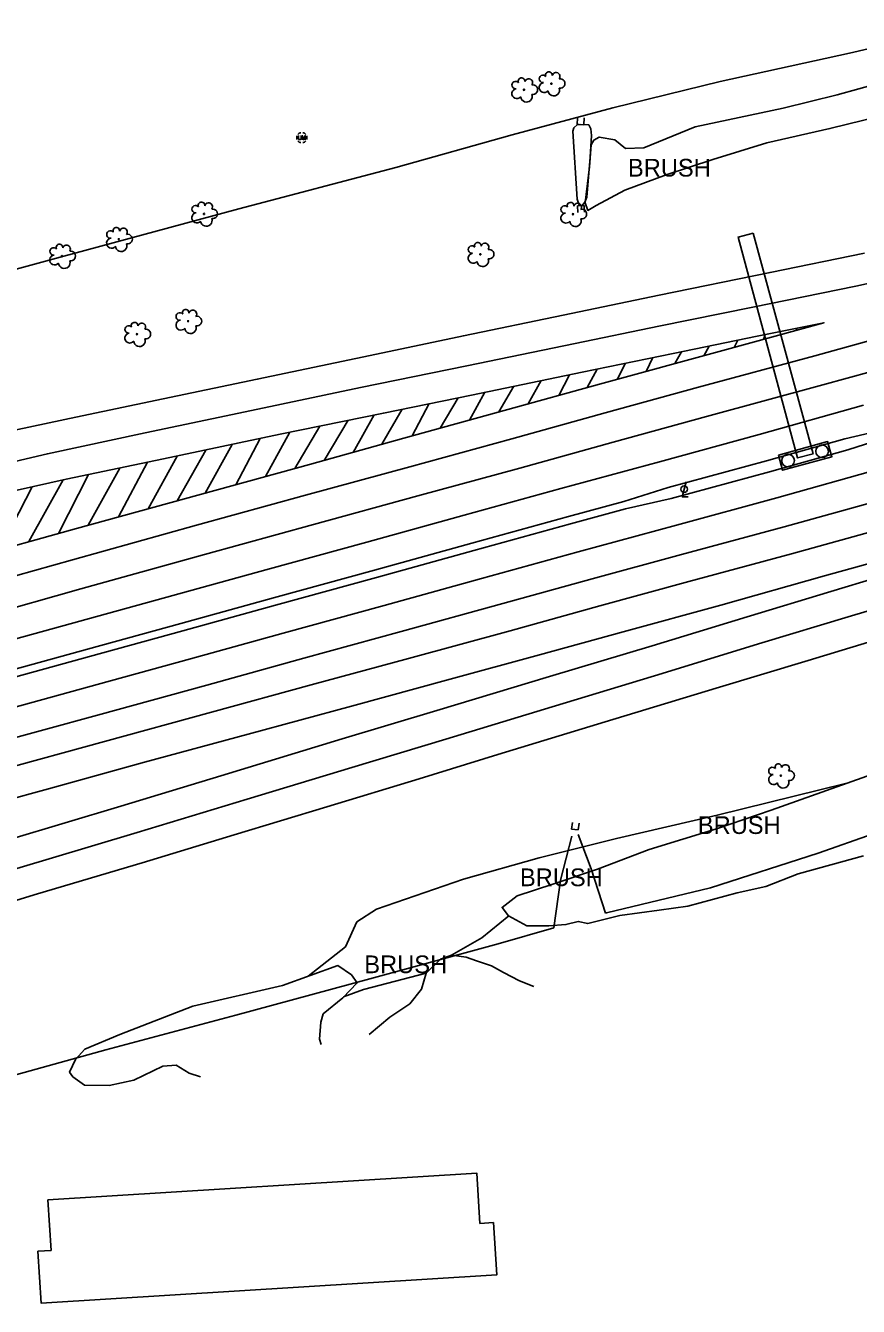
# Model space of a CAD drawing. Extents: x 2129547 to 2134906, y 657330 to 659734.
# Drawn here: x 2133745 to 2134075, y 658623 to 659130 of the extents above; entities that cross this region are included whole.
import ezdxf

# ---------------------------------------------------------------- set-up
doc = ezdxf.new("R2010")
doc.units = 0
for name, color, linetype in [('BD_X_Building', 7, 'Continuous'), ('Default', 7, 'Continuous'), ('DR_X_Culvert', 7, 'Continuous'), ('HY_X_Water_Edge', 7, 'Continuous'), ('LT_X_Poles', 7, 'Continuous'), ('PM_X_Edge_Line', 7, 'Continuous'), ('PM_X_Lane_Line', 7, 'Continuous'), ('PM_X_Transverse_Line', 7, 'Continuous'), ('PV_X_EOP2', 7, 'Continuous'), ('RD_X_Concrete_Barrier', 7, 'Continuous'), ('RD_X_Fence', 7, 'Continuous'), ('SN_X_Foundation', 7, 'Continuous'), ('SN_X_Truss_Overhead', 7, 'Continuous'), ('UT_X_Unknown_Cells', 7, 'Continuous'), ('VG_X_Cells', 7, 'Continuous'), ('VG_X_Shrub_Line_Lt', 7, 'Continuous'), ('VG_X_Text', 7, 'Continuous'), ('VG_X_Tree_Line_Lt', 7, 'Continuous')]:
    doc.layers.add(name, color=color, linetype=linetype)

# ---------------------------------------------------------------- blocks, each defined once
blk = doc.blocks.new('PIPE')
at = {"layer": 'Default'}
for p, q in [((0.135, 0.067), (0, 0.067)), ((0, 0.067), (0, -0.067)), ((0, -0.067), (0.135, -0.067))]:
    blk.add_line(p, q, dxfattribs=at)
blk = doc.blocks.new('LPOLE')
at = {"layer": 'LT_X_Poles'}
blk.add_lwpolyline([(0.01, 0.0375), (-0.01, -0.0385), (0.02, -0.0385)], dxfattribs=at)
blk.add_circle((0, 0), 0.0165, dxfattribs=at)
blk = doc.blocks.new('TREE')
at = {"layer": 'VG_X_Cells'}
blk.add_circle((0, 0), 0.00305, dxfattribs=at)
for centre, radius, start, end in [((-0.0362, -0.0197), 0.0251, 96.17219, 320.57371), ((-0.042, 0.0237), 0.0187, 39.06254, 279.54124), ((-0.0125, 0.0428), 0.0167, 354.0047, 205.97412), ((0.0232, 0.0359), 0.0197, 323.82996, 165.0376), ((0.0439, 0.0005), 0.0243, 259.14531, 101.45961), ((0.012, -0.0331), 0.029, 184.94757, 19.45715)]:
    blk.add_arc(centre, radius, start, end, dxfattribs=at)
blk = doc.blocks.new('UMH')
at = {"layer": 'UT_X_Unknown_Cells'}
for p, q in [((-0.017, 0.0104), (-0.017, -0.0059)), ((-0.0042, 0.0104), (-0.0042, -0.0059))]:
    blk.add_line(p, q, dxfattribs=at)
blk.add_lwpolyline([(0.0024, -0.01), (0.0024, 0.0104), (0.0099, -0.01), (0.0174, 0.0104), (0.0174, -0.01)], dxfattribs=at)
for centre, radius, start, end in [((0, 0), 0.0254, 160.01689, 200.03919), ((0, 0), 0.0254, 100.0806, 140.07213), ((0, 0), 0.0254, 40.05767, 80.10608), ((0, 0), 0.0254, 340.01689, 20.03919), ((0, 0), 0.0254, 220.05767, 260.04731), ((-0.0106, -0.0029), 0.00708, 205.19243, 334.80757), ((0, 0), 0.0254, 280.01144, 320.02638)]:
    blk.add_arc(centre, radius, start, end, dxfattribs=at)
blk = doc.blocks.new('POINT_DISPLAY')
at = {"layer": 'Default'}
blk.add_line((0, 0), (0, 0), dxfattribs=at)
blk = doc.blocks.new('STFN_7.65-57X')
at = {"layer": 'Default'}
blk.add_lwpolyline([(-1.027, 0.318), (1.027, 0.318), (1.027, -0.317), (-1.027, -0.317)], close=True, dxfattribs=at)
for centre in [(-0.709, 0), (0.709, 0)]:
    blk.add_circle(centre, 0.254, dxfattribs=at)
blk.add_blockref('POINT_DISPLAY', (0, 0), dxfattribs=at)

msp = doc.modelspace()

# ---------------------------------------------------------------- linework, layer by layer
at = {"layer": 'BD_X_Building'}
msp.add_lwpolyline([(2133753.79, 658665.45), (2133923.53, 658676), (2133924.77, 658656.08), (2133930.12, 658656.42), (2133931.41, 658635.72), (2133751.11, 658624.52), (2133749.83, 658645.09), (2133755.03, 658645.41)], close=True, dxfattribs=at)
at = {"layer": 'HY_X_Water_Edge'}
for points in [[(2133964.19, 659058.89), (2133963.21, 659061.53), (2133961.53, 659088.43), (2133961.95, 659089.65), (2133963.33, 659091.05), (2133964.03, 659091.04)], [(2133965.25, 659058.94), (2133966.24, 659060.31), (2133967.09, 659062.25), (2133968.4, 659078.09), (2133968.88, 659086.71), (2133968.68, 659089.37), (2133967.8, 659090.87), (2133964.39, 659091)]]:
    msp.add_lwpolyline(points, dxfattribs=at)
at = {"layer": 'PM_X_Edge_Line'}
for points in [[(2134076.98, 659040.11), (2134039.58, 659032.47), (2133995.73, 659023.51), (2133957.76, 659015.59), (2133918.23, 659007.39), (2133881.38, 658999.63), (2133836.62, 658990.22), (2133799.43, 658982.49), (2133764.9, 658975.21), (2133735.74, 658968.93), (2133703.2, 658961.23), (2133666.48, 658951.71), (2133630.91, 658941.98), (2133596.74, 658932.79), (2133563.73, 658923.72), (2133529.99, 658914.34), (2133494.1, 658904.34), (2133466.6, 658896.85), (2133432.86, 658887.72), (2133403.89, 658879.94), (2133374.41, 658872.42), (2133346.49, 658865.44), (2133329.04, 658861.1), (2133300.92, 658854.17)], [(2133722.33, 658919.3), (2133765.05, 658931.14), (2133807.8, 658942.86), (2133857.32, 658956.46), (2133894.64, 658966.9), (2133935.83, 658978.22), (2133972.12, 658988.26), (2134020.83, 659001.53), (2134060.85, 659012.54), (2134034.42, 659007.23), (2134001.29, 659000.44), (2133965.24, 658993), (2133921.46, 658983.96), (2133886.55, 658976.83), (2133845.67, 658968.4), (2133799.54, 658958.66), (2133761.03, 658950.6), (2133728.54, 658943.33)], [(2133309.7, 658768.6), (2133347.5, 658778.96), (2133367.51, 658784.47), (2133405.62, 658795.16), (2133448.61, 658806.96), (2133483.46, 658816.51), (2133522.93, 658827.51), (2133562.53, 658838.54), (2133602.55, 658849.42), (2133643.3, 658860.47), (2133686.86, 658872.53), (2133725.64, 658883.22), (2133766.44, 658894.43), (2133803.3, 658904.62), (2133840.04, 658914.78), (2133879.97, 658925.74), (2133918.52, 658936.37), (2133956.82, 658946.94), (2133995.76, 658957.55), (2134035.26, 658968.3), (2134076.56, 658979.89)], [(2134083.48, 658954.83), (2134042.19, 658943.24), (2134002.59, 658932.46), (2133963.69, 658921.87), (2133925.43, 658911.31), (2133886.87, 658900.67), (2133846.95, 658889.72), (2133810.23, 658879.56), (2133773.34, 658869.36), (2133732.54, 658858.16), (2133693.78, 658847.47), (2133650.17, 658835.4), (2133609.36, 658824.33), (2133569.43, 658813.47), (2133529.91, 658802.46), (2133490.38, 658791.45), (2133455.49, 658781.89), (2133412.58, 658770.11), (2133374.05, 658759.3), (2133354.39, 658753.89), (2133316.59, 658743.53), (2133275.25, 658732.12)], [(2133283.96, 658698.16), (2133325.94, 658709.93), (2133362.52, 658720.04), (2133382.76, 658725.75), (2133415.39, 658734.86), (2133446.49, 658743.43), (2133481, 658753.01), (2133515.88, 658762.68), (2133547.13, 658771.3), (2133583.28, 658781.31), (2133617.02, 658790.56), (2133648.77, 658799.18), (2133685.56, 658809.34), (2133717.23, 658818.06), (2133753.97, 658828.1), (2133791.98, 658838.6), (2133832.99, 658849.73), (2133873.96, 658860.85), (2133913, 658871.48), (2133948.28, 658881.16), (2133981.44, 658890.27), (2134020.14, 658900.81), (2134061.11, 658912.35), (2134098.82, 658922.76)], [(2134100.25, 658917.23), (2134063.61, 658906.19), (2134030.5, 658896.13), (2133992.93, 658884.72), (2133952.23, 658872.51), (2133907.65, 658859.14), (2133870.19, 658847.84), (2133822.17, 658833.24), (2133782.71, 658821.22), (2133738.55, 658807.98), (2133692.7, 658794.41), (2133654.59, 658783.4), (2133617.25, 658772.7), (2133577.18, 658761.03), (2133541.61, 658750.79), (2133494, 658737.03), (2133462.99, 658727.98), (2133431.79, 658718.75), (2133387.92, 658705.89), (2133365.27, 658699.28), (2133330.15, 658689.11), (2133297.63, 658679.74)], [(2133300.81, 658650.13), (2133340.17, 658662.31), (2133370.93, 658671.87), (2133394.87, 658679.11), (2133427.09, 658689.08), (2133460.97, 658699.4), (2133496.37, 658710.22), (2133532.31, 658721.07), (2133564.53, 658730.83), (2133600.72, 658741.62), (2133635.89, 658752.26), (2133677.52, 658764.71), (2133710.02, 658774.41), (2133749.64, 658786.47), (2133791.16, 658798.85), (2133827.56, 658809.83), (2133864.21, 658820.91), (2133900.69, 658832.03), (2133931.82, 658841.63), (2133974.36, 658854.66), (2134018.27, 658867.93), (2134054.66, 658878.9), (2134088.9, 658889.31)]]:
    msp.add_lwpolyline(points, dxfattribs=at)
at = {"layer": 'PM_X_Lane_Line'}
for points in [[(2134118.93, 659037.07), (2134073.54, 659027.1), (2134032.75, 659018.71), (2133995.61, 659011.27), (2133962.39, 659004.33), (2133919.52, 658995.52), (2133877.54, 658986.95), (2133831.82, 658977.28), (2133792.35, 658968.95), (2133753.58, 658960.7), (2133718.63, 658952.54), (2133687.93, 658944.98), (2133659.01, 658937.36), (2133625.24, 658928.09), (2133585.58, 658917.3), (2133543.69, 658905.93), (2133507.33, 658895.86), (2133466.3, 658884.59), (2133424.01, 658873.52), (2133383.54, 658862.9), (2133349.44, 658854.08), (2133325.82, 658848.04), (2133297.69, 658840.83)], [(2133313.7, 658795.31), (2133339, 658802.3), (2133361.28, 658808.47), (2133395.15, 658817.54), (2133438.07, 658829.18), (2133482.76, 658841.53), (2133526.2, 658853.67), (2133575.25, 658867.16), (2133621.71, 658879.84), (2133678.02, 658895.07), (2133725.8, 658908.19), (2133763.55, 658918.78), (2133812.61, 658932.39), (2133855.72, 658944.34), (2133897.07, 658955.57), (2133937.39, 658966.63), (2133974.36, 658976.85), (2134011.24, 658987.04), (2134057.34, 658999.52), (2134095.74, 659010.12)], [(2134098.91, 658998.55), (2134060.5, 658987.95), (2134014.41, 658975.46), (2133977.55, 658965.28), (2133940.57, 658955.06), (2133900.23, 658943.99), (2133858.89, 658932.76), (2133815.81, 658920.83), (2133766.78, 658907.22), (2133728.61, 658896.45), (2133681.16, 658883.49), (2133624.85, 658868.26), (2133578.42, 658855.58), (2133529.4, 658842.11), (2133485.97, 658829.97), (2133441.24, 658817.61), (2133398.31, 658805.97), (2133364.46, 658796.21), (2133347.75, 658791.48), (2133325.2, 658785.49), (2133298.77, 658778.04)], [(2134082.7, 658942.15), (2134045.11, 658931.76), (2134004.55, 658920.87), (2133969.21, 658911.2), (2133933.79, 658901.38), (2133893.59, 658890.3), (2133855.02, 658879.79), (2133816.65, 658869.07), (2133773.41, 658857.23), (2133730.82, 658845.66), (2133696.89, 658836.35), (2133666.57, 658827.89), (2133635.33, 658819.28), (2133597.94, 658809.08), (2133562.69, 658799.56), (2133526.89, 658789.25), (2133487.16, 658778.31), (2133449.31, 658767.99), (2133406.68, 658756.3), (2133376.98, 658748.02), (2133351.87, 658741.08), (2133319.94, 658732.31), (2133288.5, 658723.61)], [(2134085.69, 658931.46), (2134048.03, 658921.05), (2134007.46, 658910.16), (2133972.15, 658900.5), (2133936.74, 658890.68), (2133896.5, 658879.69), (2133857.94, 658869.19), (2133818.5, 658858.38), (2133776.26, 658846.81), (2133733.66, 658835.25), (2133699.77, 658825.94), (2133669.46, 658817.48), (2133638.19, 658808.87), (2133600.77, 658798.65), (2133565.6, 658789.16), (2133529.81, 658778.86), (2133490.02, 658767.9), (2133452.16, 658757.57), (2133409.55, 658745.89), (2133379.74, 658737.38), (2133360.24, 658732.07), (2133330.22, 658723.85), (2133298.5, 658714.96)], [(2133285.43, 658660.84), (2133325.6, 658673.06), (2133366.78, 658685.54), (2133391.32, 658692.78), (2133423.26, 658702.17), (2133460.05, 658712.86), (2133499.85, 658724.58), (2133554.8, 658740.88), (2133599.29, 658754.21), (2133636.1, 658765.28), (2133676.03, 658777.16), (2133716.18, 658788.97), (2133754.3, 658800.38), (2133789.1, 658810.81), (2133832.71, 658824.03), (2133874.01, 658836.57), (2133911.3, 658847.78), (2133953.4, 658860.48), (2133993.83, 658872.75), (2134036.36, 658885.82), (2134070.45, 658896.19), (2134110.34, 658908.07)]]:
    msp.add_lwpolyline(points, dxfattribs=at)
at = {"layer": 'PM_X_Transverse_Line'}
for p, q in [((2134036.98, 659005.98), (2134037.61, 659007.87)), ((2134049.85, 659009.52), (2134050.12, 659010.39)), ((2134013.42, 658999.52), (2134015.51, 659003.35)), ((2134025.38, 659002.78), (2134026.84, 659005.68)), ((2133990.54, 658993.28), (2133993.18, 658998.77)), ((2134001.92, 658996.38), (2134004.51, 659001.1)), ((2133955.94, 658983.79), (2133960.22, 658991.96)), ((2133967.2, 658986.9), (2133971.21, 658994.23)), ((2133979.04, 658990.15), (2133982.42, 658996.55)), ((2133932.27, 658977.24), (2133938.13, 658987.4)), ((2133943.88, 658980.45), (2133949, 658989.65)), ((2133909.08, 658970.87), (2133916.15, 658982.87)), ((2133920.66, 658974.05), (2133926.68, 658985.04)), ((2133885.99, 658964.49), (2133893.98, 658978.35)), ((2133897.94, 658967.81), (2133904.73, 658980.54)), ((2133851.55, 658954.88), (2133861.45, 658971.65)), ((2133863.12, 658958.09), (2133872.61, 658973.96)), ((2133874.66, 658961.2), (2133882.87, 658976.07)), ((2133828.15, 658948.45), (2133837.79, 658966.74)), ((2133839.97, 658951.7), (2133849.56, 658969.2)), ((2133805.01, 658942.09), (2133816.26, 658962.19)), ((2133816, 658945.11), (2133826.72, 658964.4)), ((2133781.78, 658935.73), (2133793.2, 658957.33)), ((2133793.45, 658938.93), (2133804.95, 658959.8)), ((2133758.04, 658929.2), (2133769.86, 658952.45)), ((2133769.76, 658932.43), (2133782.3, 658955.05)), ((2133734.58, 658922.69), (2133747.58, 658947.59)), ((2133746.3, 658925.94), (2133759.81, 658950.33))]:
    msp.add_line(p, q, dxfattribs=at)
at = {"layer": 'PV_X_EOP2'}
for points in [[(2134076.98, 659040.11), (2134039.58, 659032.47), (2133995.73, 659023.51), (2133957.76, 659015.59), (2133918.23, 659007.39), (2133881.38, 658999.63), (2133836.62, 658990.22), (2133799.43, 658982.49), (2133764.9, 658975.21), (2133735.74, 658968.93), (2133703.2, 658961.23), (2133666.48, 658951.71), (2133630.91, 658941.98), (2133596.74, 658932.79), (2133563.73, 658923.72), (2133529.99, 658914.34), (2133494.1, 658904.34), (2133466.6, 658896.85), (2133432.86, 658887.72), (2133403.89, 658879.94), (2133374.41, 658872.42), (2133346.49, 658865.44), (2133329.04, 658861.1), (2133300.92, 658854.17)], [(2133722.33, 658919.3), (2133765.05, 658931.14), (2133807.8, 658942.86), (2133857.32, 658956.46), (2133894.64, 658966.9), (2133935.83, 658978.22), (2133972.12, 658988.26), (2134020.83, 659001.53), (2134060.85, 659012.54), (2134034.42, 659007.23), (2134001.29, 659000.44), (2133965.24, 658993), (2133921.46, 658983.96), (2133886.55, 658976.83), (2133845.67, 658968.4), (2133799.54, 658958.66), (2133761.03, 658950.6), (2133728.54, 658943.33)], [(2133309.7, 658768.6), (2133347.5, 658778.96), (2133367.51, 658784.47), (2133405.62, 658795.16), (2133448.61, 658806.96), (2133483.46, 658816.51), (2133522.93, 658827.51), (2133562.53, 658838.54), (2133602.55, 658849.42), (2133643.3, 658860.47), (2133686.86, 658872.53), (2133725.64, 658883.22), (2133766.44, 658894.43), (2133803.3, 658904.62), (2133840.04, 658914.78), (2133879.97, 658925.74), (2133918.52, 658936.37), (2133956.82, 658946.94), (2133995.76, 658957.55), (2134035.26, 658968.3), (2134076.56, 658979.89)], [(2134083.48, 658954.83), (2134042.19, 658943.24), (2134002.59, 658932.46), (2133963.69, 658921.87), (2133925.43, 658911.31), (2133886.87, 658900.67), (2133846.95, 658889.72), (2133810.23, 658879.56), (2133773.34, 658869.36), (2133732.54, 658858.16), (2133693.78, 658847.47), (2133650.17, 658835.4), (2133609.36, 658824.33), (2133569.43, 658813.47), (2133529.91, 658802.46), (2133490.38, 658791.45), (2133455.49, 658781.89), (2133412.58, 658770.11), (2133374.05, 658759.3), (2133354.39, 658753.89), (2133316.59, 658743.53), (2133275.25, 658732.12)], [(2133283.96, 658698.16), (2133325.94, 658709.93), (2133362.52, 658720.04), (2133382.76, 658725.75), (2133415.39, 658734.86), (2133446.49, 658743.43), (2133481, 658753.01), (2133515.88, 658762.68), (2133547.13, 658771.3), (2133583.28, 658781.31), (2133617.02, 658790.56), (2133648.77, 658799.18), (2133685.56, 658809.34), (2133717.23, 658818.06), (2133753.97, 658828.1), (2133791.98, 658838.6), (2133832.99, 658849.73), (2133873.96, 658860.85), (2133913, 658871.48), (2133948.28, 658881.16), (2133981.44, 658890.27), (2134020.14, 658900.81), (2134061.11, 658912.35), (2134098.82, 658922.76)], [(2134100.25, 658917.23), (2134063.61, 658906.19), (2134030.5, 658896.13), (2133992.93, 658884.72), (2133952.23, 658872.51), (2133907.65, 658859.14), (2133870.19, 658847.84), (2133822.17, 658833.24), (2133782.71, 658821.22), (2133738.55, 658807.98), (2133692.7, 658794.41), (2133654.59, 658783.4), (2133617.25, 658772.7), (2133577.18, 658761.03), (2133541.61, 658750.79), (2133494, 658737.03), (2133462.99, 658727.98), (2133431.79, 658718.75), (2133387.92, 658705.89), (2133365.27, 658699.28), (2133330.15, 658689.11), (2133297.63, 658679.74)]]:
    msp.add_lwpolyline(points, dxfattribs=at)
at = {"layer": 'RD_X_Concrete_Barrier'}
for points in [[(2134087.23, 658970.87), (2134069.21, 658966.66), (2134038.13, 658957.94), (2133999.27, 658947.36), (2133981.65, 658941.79), (2133959.86, 658935.85), (2133921.58, 658925.29), (2133883.02, 658914.65), (2133843.09, 658903.7), (2133806.36, 658893.54), (2133769.49, 658883.34), (2133728.69, 658872.14)], [(2133729.49, 658869.24), (2133770.29, 658880.45), (2133807.16, 658890.65), (2133843.89, 658900.81), (2133883.82, 658911.76), (2133922.37, 658922.4), (2133960.65, 658932.96), (2133982.4, 658938.88), (2134000.4, 658943.01), (2134039.33, 658953.6), (2134070.34, 658962.31), (2134087.99, 658967.97)]]:
    msp.add_lwpolyline(points, dxfattribs=at)
at = {"layer": 'RD_X_Fence'}
for points in [[(2134118.14, 659130.16), (2134070.98, 659119.25), (2134019.86, 659107.98), (2133977.41, 659097.6), (2133937.58, 659086.88), (2133891.52, 659073.98), (2133829.38, 659057.65), (2133758.68, 659038.54), (2133682.08, 659017.72), (2133636.81, 659005.08), (2133582.59, 658990.71), (2133537.62, 658978.61), (2133480.02, 658962.66), (2133435.74, 658950.56), (2133375.25, 658933.98), (2133331.89, 658921.65)], [(2133974.46, 658778.93), (2133974.8, 658779.03), (2134016.03, 658788.92), (2134058.67, 658802.57), (2134123.95, 658825.55), (2134174.2, 658844.34), (2134189.88, 658850.21)], [(2133954.07, 658773.11), (2133956.68, 658791.99), (2133961.18, 658809.29)], [(2133963.69, 658810.06), (2133968.84, 658796.37), (2133974.46, 658778.93)], [(2133409.37, 658623.24), (2133432.34, 658629.66), (2133487.07, 658644.47), (2133549.03, 658661.67), (2133595.11, 658674.24), (2133645.48, 658687.97), (2133677.95, 658697.17), (2133733.37, 658712.84), (2133776.67, 658724.79), (2133828.23, 658738.5), (2133881.21, 658752.85), (2133931.92, 658766.78), (2133954.07, 658773.11)]]:
    msp.add_lwpolyline(points, dxfattribs=at)
at = {"layer": 'SN_X_Truss_Overhead'}
msp.add_lwpolyline([(2134032.9, 659047.96), (2134056.6, 658960.66), (2134050.47, 658959.07), (2134026.9, 659046.46)], close=True, dxfattribs=at)
at = {"layer": 'VG_X_Shrub_Line_Lt'}
for points in [[(2134083.19, 659094.34), (2134063.23, 659089.41), (2134038.23, 659083.78), (2134016.92, 659077.15), (2133998.48, 659071.17), (2133982.15, 659065.1), (2133970.7, 659058.93), (2133967.51, 659056.99), (2133966.47, 659060.05), (2133968.15, 659074.33), (2133968.74, 659082.95), (2133969.85, 659084.84), (2133972.01, 659086.02), (2133978.2, 659084.96), (2133982.43, 659081.5), (2133989.6, 659081.76), (2134009.87, 659090.07), (2134044.71, 659097.51), (2134066.18, 659102.82), (2134100.45, 659112.32)], [(2133856.76, 658753.91), (2133871.57, 658765.57), (2133876.08, 658775.4), (2133883.83, 658780.45), (2133918.32, 658792.27), (2133948.21, 658800.74), (2133978.8, 658808.41), (2134018.67, 658817.61), (2134069.43, 658830.15)], [(2133936.22, 658777.76), (2133925.5, 658769.05), (2133913.54, 658762.26)], [(2133903.47, 658755.16), (2133878.64, 658748.6), (2133870.81, 658745.7)]]:
    msp.add_lwpolyline(points, dxfattribs=at)
at = {"layer": 'VG_X_Tree_Line_Lt'}
for points in [[(2134076.6, 658801.57), (2134050.63, 658794.46), (2134037.88, 658789.46), (2134026.55, 658786.89), (2134006.98, 658781.71), (2133995.71, 658780), (2133980.15, 658777.92), (2133967.44, 658774.75), (2133963.64, 658775.61), (2133958.8, 658774.35), (2133952.07, 658773.84), (2133943.34, 658773.88), (2133936.13, 658777.81), (2133933.55, 658781.16), (2133939.44, 658785.74), (2133953.59, 658790.38), (2133971.24, 658796.23), (2133991.67, 658804.01), (2134018.38, 658812.27), (2134039.95, 658819.69), (2134081.89, 658834.58)], [(2133880.87, 658730.81), (2133889.16, 658737.75), (2133897.04, 658743), (2133901.68, 658748.83), (2133903.47, 658755.16), (2133909.12, 658760.64), (2133913.54, 658762.26), (2133919.31, 658761.42), (2133923.36, 658760.01), (2133929.31, 658757.98), (2133934.04, 658755.39), (2133940.44, 658752.03), (2133946.08, 658749.85)], [(2133782.2, 658730.89), (2133811.11, 658742.02), (2133846.64, 658750.28), (2133868.54, 658758.13), (2133873.89, 658754.49), (2133876.2, 658751.27), (2133870.47, 658745.35), (2133862.77, 658739), (2133861.74, 658735.78), (2133861.21, 658728.98), (2133861.92, 658726.85)], [(2133814.12, 658714.03), (2133809.66, 658715.54), (2133804.55, 658718.75), (2133799.24, 658718.35), (2133787.82, 658712.83), (2133778.1, 658710.68), (2133768.22, 658710.79), (2133763.68, 658714.14), (2133762.37, 658715.88), (2133764.74, 658720.92), (2133768.46, 658725.08), (2133782.2, 658730.89)]]:
    msp.add_lwpolyline(points, dxfattribs=at)

# ---------------------------------------------------------------- block references
at = {"layer": 'DR_X_Culvert'}
for p, xscale, yscale, rotation in [((2133964.56, 659091.01), 19.685, 19.68500000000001, 87.27971659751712), ((2133964.72, 659058.92), 19.685000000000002, 19.68500000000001, -87.29840511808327), ((2133962.36, 658812.03), 19.685000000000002, 19.685000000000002, 83.60147266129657)]:
    msp.add_blockref('PIPE', p, dxfattribs=dict(at, xscale=xscale, yscale=yscale, rotation=rotation))
at = {"layer": 'LT_X_Poles', "xscale": 78.74000000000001, "yscale": 78.74000000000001}
msp.add_blockref('LPOLE', (2134005.58, 658946.66), dxfattribs=at)
at = {"layer": 'SN_X_Foundation', "xscale": 9.8425, "yscale": 9.842500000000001, "rotation": 15.403226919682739}
msp.add_blockref('STFN_7.65-57X', (2134053.45, 658959.85), dxfattribs=at)
at = {"layer": 'UT_X_Unknown_Cells', "xscale": 78.74000000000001, "yscale": 78.74000000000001}
msp.add_blockref('UMH', (2133854.29, 659085.81), dxfattribs=at)
at = {"layer": 'VG_X_Cells', "xscale": 78.74000000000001, "yscale": 78.74000000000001}
for p in [(2133942.22, 659104.78), (2133953.04, 659107.21), (2133815.55, 659055.63), (2133961.62, 659055.53), (2133781.85, 659045.62), (2133759.34, 659038.94), (2133924.92, 659039.66), (2133809.3, 659013.17), (2133789.08, 659008.05), (2134043.83, 658833.28)]:
    msp.add_blockref('TREE', p, dxfattribs=at)

# ---------------------------------------------------------------- texts
at = {"layer": 'VG_X_Text'}
for p in [(2133983.34, 659070.42), (2134010.99, 658810.23), (2133940.6, 658789.56), (2133879.01, 658755.12)]:
    msp.add_text('BRUSH', height=7, dxfattribs=at).set_placement(p)

doc.saveas('drawing.dxf')
